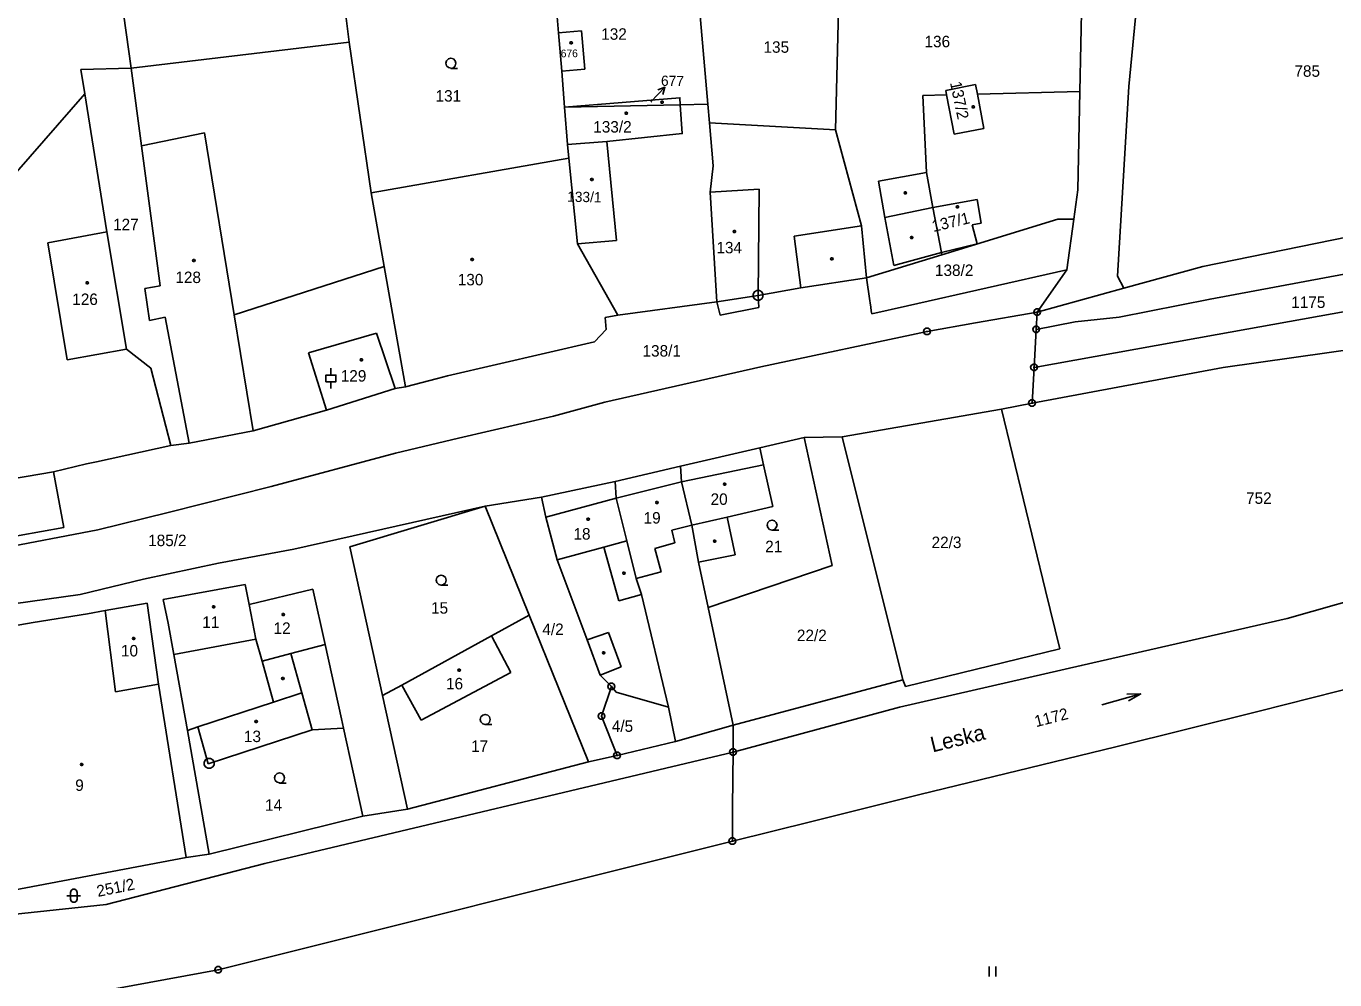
# Model space of a CAD drawing. Extents: x -812394 to -807601, y -1013098 to -1009266.
# Drawn here: x -809612.2 to -809418.3, y -1010813 to -1010671.6 of the extents above; entities that cross this region are included whole.
import ezdxf

# ---------------------------------------------------------------- set-up
doc = ezdxf.new("R2010")
doc.units = 0
for name, color, linetype in [('KN_HRANICE', 7, 'Continuous'), ('KN_KULTURY', 7, 'Continuous'), ('KN_MEZNIKY', 7, 'Continuous'), ('KN_PARCELY', 7, 'Continuous'), ('KN_SLUCKY', 7, 'Continuous')]:
    doc.layers.add(name, color=color, linetype=linetype)

# ---------------------------------------------------------------- blocks, each defined once
blk = doc.blocks.new('101')
blk.add_line((-0.05, 0), (0.05, 0))
blk.add_lwpolyline([(0.19, 0.72), (0.53, 0.53), (0.72, 0.19), (0.72, -0.2), (0.53, -0.54), (0.19, -0.73), (-0.2, -0.73), (-0.54, -0.54), (-0.73, -0.2), (-0.73, 0.19), (-0.54, 0.53), (-0.2, 0.72), (0.19, 0.72)])
blk = doc.blocks.new('304')
blk.add_lwpolyline([(0, 0), (-0.38, 0.1), (-0.65, 0.37), (-0.75, 0.74), (-0.65, 1.11), (-0.38, 1.38), (-0.01, 1.48), (0.36, 1.38), (0.63, 1.11), (0.73, 0.73), (0.63, 0.35), (0.36, 0.08), (-0.02, -0.02), (0.98, -0.02)])
blk = doc.blocks.new('306')
for p, q in [((-0.5, 1.5), (-0.5, 0)), ((0.5, 0), (0.5, 1.5))]:
    blk.add_line(p, q)
blk = doc.blocks.new('316')
for points in [[(-0.5, 1.5), (-0.4, 1.79), (-0.15, 1.97), (0.16, 1.97), (0.41, 1.79), (0.51, 1.5), (0.51, 0.5), (0.41, 0.21), (0.16, 0.03), (-0.15, 0.03), (-0.4, 0.21), (-0.5, 0.5), (-0.5, 1.5)], [(-1, 1), (0.27, 1), (1, 1)]]:
    blk.add_lwpolyline(points)
blk = doc.blocks.new('NAHRADNI_SYMBOL')
blk.add_lwpolyline([(0.09, 0.15), (0.18, 0), (0.09, -0.15), (-0.09, -0.15), (-0.18, 0), (-0.09, 0.15), (0.09, 0.15)])
blk = doc.blocks.new('802')
blk.add_line((-3, 0), (3, 0))
blk.add_lwpolyline([(1, 0.5), (3, 0), (1, -0.5)])
blk = doc.blocks.new('10292')
blk.add_line((0, 3), (0, 0))
blk.add_lwpolyline([(-0.5, 2), (0, 3), (0.5, 2)])
blk = doc.blocks.new('318')
blk.add_line((0, 2), (0, 3))
blk.add_lwpolyline([(0, 0), (0, 1), (-0.75, 1), (-0.75, 2), (0, 2), (0.75, 2), (0.75, 1), (0, 1)])
blk = doc.blocks.new('402')
blk.add_lwpolyline([(0.09, 0.15), (0.18, 0), (0.09, -0.15), (-0.09, -0.15), (-0.18, 0), (-0.09, 0.15), (0.09, 0.15)])
blk = doc.blocks.new('105')
blk.add_line((-0.12, 0), (0.12, 0))
blk.add_lwpolyline([(0.15, 0.48), (0.4, 0.3), (0.5, 0.01), (0.4, -0.28), (0.15, -0.46), (-0.16, -0.46), (-0.41, -0.28), (-0.51, 0.01), (-0.41, 0.3), (-0.16, 0.48), (0.15, 0.48)])

msp = doc.modelspace()

# ---------------------------------------------------------------- linework, layer by layer
at = {"layer": 'KN_HRANICE'}
for p, q in [((-809448.82, -1010680.59), (-809445.9, -1010650.77)), ((-809511.21, -1010683.19), (-809513.45, -1010657.55)), ((-809491.57, -1010658.3), (-809492.27, -1010687)), ((-809534.45, -1010658.78), (-809533.33, -1010672.61)), ((-809564.36, -1010674), (-809565.97, -1010661.03)), ((-809456.08, -1010681.32), (-809455.72, -1010664.14)), ((-809598.46, -1010664.88), (-809596.67, -1010677.83)), ((-809561.08, -1010696.34), (-809564.36, -1010674)), ((-809533.33, -1010672.61), (-809532.87, -1010678.29)), ((-809596.67, -1010677.83), (-809604.12, -1010678.05)), ((-809604.12, -1010678.05), (-809603.55, -1010681.64)), ((-809596.67, -1010677.83), (-809595.14, -1010689.36)), ((-809532.87, -1010678.29), (-809532.44, -1010683.62)), ((-809603.55, -1010681.64), (-809600.29, -1010702.1)), ((-809479.37, -1010681.9), (-809475.82, -1010681.81)), ((-809478.82, -1010693.3), (-809479.37, -1010681.9)), ((-809475.94, -1010681.16), (-809471.53, -1010680.26)), ((-809475.82, -1010681.81), (-809475.94, -1010681.16)), ((-809474.7, -1010687.64), (-809475.82, -1010681.81)), ((-809471.53, -1010680.26), (-809471.26, -1010681.7)), ((-809471.26, -1010681.7), (-809456.08, -1010681.32)), ((-809471.26, -1010681.7), (-809470.29, -1010686.8)), ((-809456.4, -1010695.91), (-809456.08, -1010681.32)), ((-809450.49, -1010708.71), (-809448.82, -1010680.59)), ((-809532.44, -1010683.62), (-809515.29, -1010683.27)), ((-809532.44, -1010683.62), (-809531.99, -1010689.19)), ((-809515.29, -1010683.27), (-809511.21, -1010683.19)), ((-809510.97, -1010685.95), (-809511.21, -1010683.19)), ((-809492.27, -1010687), (-809510.97, -1010685.95)), ((-809510.41, -1010692.32), (-809510.97, -1010685.95)), ((-809492.27, -1010687), (-809488.44, -1010701.23)), ((-809470.29, -1010686.8), (-809474.7, -1010687.64)), ((-809595.14, -1010689.36), (-809592.38, -1010710.12)), ((-809531.99, -1010689.19), (-809526.16, -1010688.74)), ((-809531.79, -1010691.19), (-809531.99, -1010689.19)), ((-809561.08, -1010696.34), (-809531.79, -1010691.19)), ((-809530.54, -1010703.91), (-809531.79, -1010691.19)), ((-809510.85, -1010696.24), (-809510.41, -1010692.32)), ((-809485.94, -1010694.61), (-809478.82, -1010693.3)), ((-809484.96, -1010700.01), (-809485.94, -1010694.61)), ((-809561.08, -1010696.34), (-809559.16, -1010707.24)), ((-809509.86, -1010712.52), (-809510.85, -1010696.24)), ((-809456.4, -1010695.91), (-809456.99, -1010700.24)), ((-809488.44, -1010701.23), (-809487.68, -1010708.94)), ((-809483.66, -1010707.09), (-809484.96, -1010700.01)), ((-809476.51, -1010705.51), (-809459.32, -1010700.23)), ((-809459.32, -1010700.23), (-809456.99, -1010700.24)), ((-809456.99, -1010700.24), (-809458, -1010707.77)), ((-809600.29, -1010702.1), (-809597.34, -1010719.54)), ((-809413.39, -1010702.26), (-809437.86, -1010707.26)), ((-809530.54, -1010703.91), (-809524.53, -1010714.47)), ((-809476.56, -1010705.21), (-809483.66, -1010707.09)), ((-809476.56, -1010705.21), (-809476.51, -1010705.51)), ((-809487.68, -1010708.94), (-809476.51, -1010705.51)), ((-809581.39, -1010714.41), (-809559.16, -1010707.24)), ((-809559.16, -1010707.24), (-809556, -1010725.11)), ((-809497.45, -1010710.44), (-809487.68, -1010708.94)), ((-809487.2, -1010712.35), (-809487.68, -1010708.94)), ((-809481.63, -1010713.11), (-809458, -1010707.77)), ((-809462.39, -1010714.03), (-809458, -1010707.77)), ((-809449.57, -1010710.49), (-809450.49, -1010708.71)), ((-809437.86, -1010707.26), (-809449.57, -1010710.49)), ((-809592.38, -1010710.12), (-809594.66, -1010710.54)), ((-809594.66, -1010710.54), (-809593.93, -1010715.27)), ((-809503.76, -1010711.54), (-809497.45, -1010710.44)), ((-809449.57, -1010710.49), (-809462.39, -1010714.03)), ((-809524.53, -1010714.47), (-809509.86, -1010712.52)), ((-809509.86, -1010712.52), (-809509.39, -1010714.47)), ((-809503.65, -1010713.32), (-809503.76, -1010711.54)), ((-809487.15, -1010712.67), (-809487.2, -1010712.35)), ((-809487.06, -1010713.28), (-809487.15, -1010712.67)), ((-809593.93, -1010715.27), (-809591.65, -1010714.79)), ((-809591.65, -1010714.79), (-809588.06, -1010733.47)), ((-809578.59, -1010731.65), (-809581.39, -1010714.41)), ((-809526.41, -1010714.85), (-809524.53, -1010714.47)), ((-809526.26, -1010716.6), (-809526.41, -1010714.85)), ((-809509.39, -1010714.47), (-809503.65, -1010713.32)), ((-809486.99, -1010713.83), (-809487.06, -1010713.28)), ((-809486.92, -1010714.3), (-809486.99, -1010713.83)), ((-809486.92, -1010714.3), (-809481.63, -1010713.11)), ((-809462.39, -1010714.03), (-809471.53, -1010715.63)), ((-809462.54, -1010716.59), (-809462.39, -1010714.03)), ((-809528.01, -1010718.45), (-809526.26, -1010716.6)), ((-809503.35, -1010722.13), (-809478.73, -1010716.9)), ((-809471.53, -1010715.63), (-809478.73, -1010716.9)), ((-809462.86, -1010722.22), (-809462.54, -1010716.59)), ((-809434.83, -1010722.26), (-809386.46, -1010715.35)), ((-809549.8, -1010723.5), (-809528.01, -1010718.45)), ((-809597.34, -1010719.54), (-809593.76, -1010722.34)), ((-809593.76, -1010722.34), (-809590.8, -1010733.81)), ((-809526.46, -1010727.38), (-809503.35, -1010722.13)), ((-809463.16, -1010727.52), (-809462.86, -1010722.22)), ((-809463.16, -1010727.52), (-809434.83, -1010722.26)), ((-809556, -1010725.11), (-809551.26, -1010723.86)), ((-809551.26, -1010723.86), (-809549.8, -1010723.5)), ((-809567.73, -1010728.55), (-809557.57, -1010725.36)), ((-809557.57, -1010725.36), (-809556, -1010725.11)), ((-809567.73, -1010728.55), (-809578.59, -1010731.65)), ((-809534.09, -1010729.46), (-809526.46, -1010727.38)), ((-809491.31, -1010732.5), (-809467.68, -1010728.42)), ((-809467.68, -1010728.42), (-809463.16, -1010727.52)), ((-809548.16, -1010732.72), (-809534.09, -1010729.46)), ((-809578.59, -1010731.65), (-809588.06, -1010733.47)), ((-809590.8, -1010733.81), (-809601.82, -1010736.22)), ((-809588.06, -1010733.47), (-809590.8, -1010733.81)), ((-809557.49, -1010734.93), (-809548.16, -1010732.72)), ((-809515.24, -1010736.89), (-809503.51, -1010734.14)), ((-809503.51, -1010734.14), (-809496.94, -1010732.6)), ((-809502.98, -1010736.65), (-809503.51, -1010734.14)), ((-809496.94, -1010732.6), (-809491.31, -1010732.5)), ((-809496.94, -1010732.6), (-809492.77, -1010751.6)), ((-809491.31, -1010732.5), (-809482.31, -1010768.54)), ((-809601.82, -1010736.22), (-809603.28, -1010736.54)), ((-809575.93, -1010739.9), (-809557.49, -1010734.93)), ((-809618.66, -1010739.51), (-809608.17, -1010737.7)), ((-809608.17, -1010737.7), (-809603.28, -1010736.54)), ((-809608.17, -1010737.7), (-809606.66, -1010745.99)), ((-809524.96, -1010739.16), (-809515.24, -1010736.89)), ((-809515.12, -1010739.21), (-809515.24, -1010736.89)), ((-809502.98, -1010736.65), (-809501.59, -1010742.84)), ((-809591.21, -1010743.76), (-809575.93, -1010739.9)), ((-809535.88, -1010741.49), (-809524.96, -1010739.16)), ((-809524.82, -1010741.63), (-809524.96, -1010739.16)), ((-809513.6, -1010745.64), (-809515.12, -1010739.21)), ((-809544.23, -1010742.79), (-809535.88, -1010741.49)), ((-809535.88, -1010741.49), (-809535.22, -1010744.44)), ((-809524.82, -1010741.63), (-809523.2, -1010747.95)), ((-809601.6, -1010746.29), (-809591.21, -1010743.76)), ((-809544.23, -1010742.79), (-809572.56, -1010749.19)), ((-809564.25, -1010748.81), (-809544.23, -1010742.79)), ((-809544.23, -1010742.79), (-809537.7, -1010758.97)), ((-809501.59, -1010742.84), (-809508.37, -1010744.41)), ((-809606.66, -1010745.99), (-809626.64, -1010749.55)), ((-809535.22, -1010744.44), (-809533.52, -1010750.77)), ((-809512.59, -1010751.13), (-809513.6, -1010745.64)), ((-809508.37, -1010744.41), (-809507.14, -1010750.01)), ((-809621.25, -1010750.05), (-809601.6, -1010746.29)), ((-809572.56, -1010749.19), (-809583.73, -1010751.27)), ((-809559.42, -1010770.87), (-809564.25, -1010748.81)), ((-809523.2, -1010747.95), (-809521.85, -1010753.55)), ((-809583.73, -1010751.27), (-809594.82, -1010753.62)), ((-809533.52, -1010750.77), (-809529.09, -1010762.64)), ((-809512.59, -1010751.13), (-809507.14, -1010750.01)), ((-809512.59, -1010751.13), (-809511.16, -1010757.85)), ((-809492.77, -1010751.6), (-809511.16, -1010757.85)), ((-809594.82, -1010753.62), (-809604.22, -1010755.92)), ((-809521.85, -1010753.55), (-809521.03, -1010755.88)), ((-809591.91, -1010756.66), (-809579.76, -1010754.43)), ((-809579.76, -1010754.43), (-809579.19, -1010757.38)), ((-809579.19, -1010757.38), (-809569.76, -1010755.12)), ((-809569.76, -1010755.12), (-809567.94, -1010763.34)), ((-809619.48, -1010758), (-809604.22, -1010755.92)), ((-809594.29, -1010757.19), (-809600.5, -1010758.29)), ((-809592.64, -1010769.19), (-809594.29, -1010757.19)), ((-809591.2, -1010760.14), (-809591.91, -1010756.66)), ((-809579.19, -1010757.38), (-809578.18, -1010762.54)), ((-809521.03, -1010755.88), (-809517.06, -1010772.62)), ((-809611.19, -1010760.06), (-809603.15, -1010758.78)), ((-809603.15, -1010758.78), (-809600.5, -1010758.29)), ((-809600.5, -1010758.29), (-809598.99, -1010770.33)), ((-809543.29, -1010762.05), (-809537.7, -1010758.97)), ((-809537.7, -1010758.97), (-809528.91, -1010780.74)), ((-809511.16, -1010757.85), (-809507.45, -1010775.29)), ((-809619.76, -1010761.5), (-809611.19, -1010760.06)), ((-809590.34, -1010764.82), (-809591.2, -1010760.14)), ((-809577.28, -1010765.78), (-809578.18, -1010762.54)), ((-809572.99, -1010764.66), (-809567.94, -1010763.34)), ((-809567.94, -1010763.34), (-809565.5, -1010774.33)), ((-809556.56, -1010769.35), (-809543.29, -1010762.05)), ((-809543.29, -1010762.05), (-809540.4, -1010767.48)), ((-809529.09, -1010762.64), (-809527.15, -1010767.85)), ((-809590.34, -1010764.82), (-809588.33, -1010776.05)), ((-809577.28, -1010765.78), (-809572.99, -1010764.66)), ((-809481.91, -1010769.54), (-809459.07, -1010763.94)), ((-809575.59, -1010771.87), (-809577.28, -1010765.78)), ((-809598.99, -1010770.33), (-809592.64, -1010769.19)), ((-809588.54, -1010794.9), (-809592.64, -1010769.19)), ((-809540.4, -1010767.48), (-809553.7, -1010774.56)), ((-809527.15, -1010767.85), (-809525.51, -1010769.54)), ((-809507.45, -1010775.29), (-809482.31, -1010768.54)), ((-809482.31, -1010768.54), (-809481.91, -1010769.54)), ((-809556.56, -1010769.35), (-809559.42, -1010770.87)), ((-809555.73, -1010787.74), (-809559.42, -1010770.87)), ((-809556.56, -1010769.35), (-809553.7, -1010774.56)), ((-809526.96, -1010773.94), (-809525.51, -1010769.54)), ((-809525.51, -1010769.54), (-809524.78, -1010770.4)), ((-809524.78, -1010770.4), (-809517.06, -1010772.62)), ((-809586.77, -1010775.53), (-809575.59, -1010771.87)), ((-809517.06, -1010772.62), (-809516.02, -1010777.68)), ((-809565.5, -1010774.33), (-809565.19, -1010775.74)), ((-809524.66, -1010779.77), (-809526.96, -1010773.94)), ((-809586.77, -1010775.53), (-809588.33, -1010776.05)), ((-809588.33, -1010776.05), (-809585.11, -1010794.39)), ((-809586.77, -1010775.53), (-809585.25, -1010781)), ((-809585.25, -1010781), (-809569.85, -1010775.96)), ((-809569.85, -1010775.96), (-809565.19, -1010775.74)), ((-809565.19, -1010775.74), (-809562.33, -1010788.78)), ((-809516.02, -1010777.68), (-809507.45, -1010775.29)), ((-809507.48, -1010779.27), (-809507.45, -1010775.29)), ((-809524.66, -1010779.77), (-809516.02, -1010777.68)), ((-809576.87, -1010795.8), (-809507.48, -1010779.27)), ((-809555.73, -1010787.74), (-809528.91, -1010780.74)), ((-809528.91, -1010780.74), (-809524.66, -1010779.77)), ((-809507.51, -1010783.2), (-809507.48, -1010779.27)), ((-809507.54, -1010787.61), (-809507.51, -1010783.2)), ((-809562.33, -1010788.78), (-809555.73, -1010787.74)), ((-809507.57, -1010792.49), (-809507.54, -1010787.61)), ((-809585.11, -1010794.39), (-809562.33, -1010788.78)), ((-809507.57, -1010792.49), (-809495.79, -1010789.54)), ((-809583.77, -1010811.56), (-809507.57, -1010792.49)), ((-809588.54, -1010794.9), (-809585.11, -1010794.39)), ((-809615.96, -1010800.09), (-809588.54, -1010794.9)), ((-809600.38, -1010801.89), (-809576.87, -1010795.8)), ((-809600.38, -1010801.89), (-809643.49, -1010806.47)), ((-809609.07, -1010816.23), (-809583.77, -1010811.56))]:
    msp.add_line(p, q, dxfattribs=at)
for points in [[(-809533.33, -1010672.61), (-809529.94, -1010672.33), (-809529.46, -1010677.99), (-809532.87, -1010678.29)], [(-809623.13, -1010728.35), (-809625.78, -1010708.61), (-809623.83, -1010704.87), (-809603.55, -1010681.64)], [(-809532.44, -1010683.62), (-809515.36, -1010682.23), (-809515.29, -1010683.27)], [(-809526.16, -1010688.74), (-809514.99, -1010687.55), (-809515.29, -1010683.27)], [(-809386.86, -1010717.18), (-809390.64, -1010734.74), (-809392.82, -1010743.13), (-809395.75, -1010747.43), (-809400.98, -1010751.89), (-809410.38, -1010755.21), (-809425.36, -1010759.45), (-809455.87, -1010766.45), (-809482.83, -1010772.6), (-809507.48, -1010779.27)], [(-809459.07, -1010763.94), (-809461.16, -1010755.31), (-809467.68, -1010728.42)], [(-809429.53, -1010773.18), (-809413.92, -1010769.26), (-809389.38, -1010761.78)], [(-809495.79, -1010789.54), (-809479.79, -1010785.54), (-809450.75, -1010778.5), (-809429.53, -1010773.18)]]:
    msp.add_lwpolyline(points, dxfattribs=at)
at = {"layer": 'KN_SLUCKY'}
for p, q in [((-809596.67, -1010677.83), (-809564.36, -1010674)), ((-809585.78, -1010687.46), (-809595.14, -1010689.36)), ((-809581.39, -1010714.41), (-809585.78, -1010687.46)), ((-809526.16, -1010688.74), (-809524.76, -1010703.42)), ((-809478.82, -1010693.3), (-809477.86, -1010698.52)), ((-809503.61, -1010695.79), (-809510.85, -1010696.24)), ((-809503.76, -1010711.54), (-809503.61, -1010695.79)), ((-809477.86, -1010698.52), (-809471.32, -1010697.32)), ((-809471.32, -1010697.32), (-809470.68, -1010700.85)), ((-809484.96, -1010700.01), (-809477.86, -1010698.52)), ((-809477.86, -1010698.52), (-809476.56, -1010705.21)), ((-809498.4, -1010702.75), (-809488.44, -1010701.23)), ((-809470.68, -1010700.85), (-809472.02, -1010701.1)), ((-809472.02, -1010701.1), (-809471.31, -1010703.88)), ((-809600.29, -1010702.1), (-809609, -1010703.76)), ((-809497.45, -1010710.44), (-809498.4, -1010702.75)), ((-809609, -1010703.76), (-809606.14, -1010721.1)), ((-809524.76, -1010703.42), (-809530.54, -1010703.91)), ((-809471.31, -1010703.88), (-809476.56, -1010705.21)), ((-809509.86, -1010712.52), (-809503.76, -1010711.54)), ((-809560.3, -1010717.14), (-809570.39, -1010720.06)), ((-809557.57, -1010725.36), (-809560.3, -1010717.14)), ((-809606.14, -1010721.1), (-809597.34, -1010719.54)), ((-809570.39, -1010720.06), (-809567.73, -1010728.55)), ((-809515.12, -1010739.21), (-809502.98, -1010736.65)), ((-809524.82, -1010741.63), (-809515.12, -1010739.21)), ((-809535.22, -1010744.44), (-809524.82, -1010741.63)), ((-809513.6, -1010745.64), (-809516.56, -1010746.35)), ((-809513.6, -1010745.64), (-809508.37, -1010744.41)), ((-809516.09, -1010748.24), (-809516.56, -1010746.35)), ((-809533.52, -1010750.77), (-809526.63, -1010748.89)), ((-809526.63, -1010748.89), (-809523.2, -1010747.95)), ((-809524.42, -1010756.83), (-809526.63, -1010748.89)), ((-809519.06, -1010749.09), (-809516.09, -1010748.24)), ((-809518.14, -1010752.55), (-809519.06, -1010749.09)), ((-809521.85, -1010753.55), (-809518.14, -1010752.55)), ((-809521.03, -1010755.88), (-809524.42, -1010756.83)), ((-809525.94, -1010761.52), (-809529.09, -1010762.64)), ((-809524.07, -1010766.63), (-809525.94, -1010761.52)), ((-809578.18, -1010762.54), (-809590.34, -1010764.82)), ((-809571.37, -1010770.49), (-809572.99, -1010764.66)), ((-809527.15, -1010767.85), (-809524.07, -1010766.63)), ((-809575.59, -1010771.87), (-809571.37, -1010770.49)), ((-809571.37, -1010770.49), (-809569.85, -1010775.96))]:
    msp.add_line(p, q, dxfattribs=at)
for points in [[(-809462.54, -1010716.59), (-809456.78, -1010715.47), (-809450.24, -1010714.77), (-809436.78, -1010712.1), (-809413.21, -1010707.7), (-809386.06, -1010702.58)], [(-809385.19, -1010708.29), (-809412.36, -1010713.13), (-809435.74, -1010717.37), (-809462.86, -1010722.22)]]:
    msp.add_lwpolyline(points, dxfattribs=at)

# ---------------------------------------------------------------- block references
at = {"layer": 'KN_KULTURY'}
for name, p in [('402', (-809531.46, -1010674.08)), ('304', (-809549.27, -1010677.86)), ('402', (-809517.99, -1010682.9)), ('402', (-809471.88, -1010683.59)), ('402', (-809523.3, -1010684.54)), ('402', (-809528.4, -1010694.35)), ('402', (-809481.95, -1010696.36)), ('402', (-809474.22, -1010698.43)), ('402', (-809507.27, -1010702.09)), ('402', (-809481.01, -1010702.97)), ('402', (-809587.39, -1010706.38)), ('NAHRADNI_SYMBOL', (-809546.13, -1010706.21)), ('402', (-809492.83, -1010706.14)), ('402', (-809603.18, -1010709.67)), ('318', (-809567.07, -1010725.36)), ('402', (-809562.55, -1010721.09)), ('402', (-809508.71, -1010739.53)), ('402', (-809518.76, -1010742.26)), ('402', (-809528.95, -1010744.75)), ('304', (-809501.69, -1010746.34)), ('402', (-809510.19, -1010747.99)), ('304', (-809550.72, -1010754.51)), ('402', (-809523.65, -1010752.72)), ('402', (-809584.45, -1010757.72)), ('NAHRADNI_SYMBOL', (-809574.13, -1010758.87)), ('402', (-809596.3, -1010762.41)), ('402', (-809526.65, -1010764.55)), ('402', (-809548.06, -1010767.1)), ('402', (-809574.2, -1010768.35)), ('402', (-809578.14, -1010774.75)), ('304', (-809544.19, -1010775.16)), ('NAHRADNI_SYMBOL', (-809604.01, -1010781.1)), ('304', (-809574.67, -1010783.84)), ('316', (-809605.18, -1010801.57)), ('306', (-809469.01, -1010812.57))]:
    msp.add_blockref(name, p, dxfattribs=at)
at = {"layer": 'KN_KULTURY', "rotation": 15.527156}
msp.add_blockref('802', (-809449.95, -1010771.45), dxfattribs=at)
at = {"layer": 'KN_MEZNIKY'}
for name, p in [('101', (-809503.76, -1010711.54)), ('105', (-809462.39, -1010714.03)), ('105', (-809478.73, -1010716.9)), ('105', (-809462.54, -1010716.59)), ('105', (-809462.86, -1010722.22)), ('105', (-809463.16, -1010727.52)), ('105', (-809525.51, -1010769.54)), ('105', (-809526.96, -1010773.94)), ('105', (-809507.48, -1010779.27)), ('101', (-809585.1, -1010780.94)), ('105', (-809524.66, -1010779.77)), ('105', (-809507.57, -1010792.49)), ('105', (-809583.77, -1010811.56))]:
    msp.add_blockref(name, p, dxfattribs=at)
at = {"layer": 'KN_PARCELY', "rotation": -43.72729700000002}
msp.add_blockref('10292', (-809519.64, -1010682.85), dxfattribs=at)

# ---------------------------------------------------------------- texts
at = {"layer": 'KN_PARCELY'}
for s, height, p in [('132', 1.7, (-809527.01, -1010673.64)), ('135', 1.7, (-809502.96, -1010675.57)), ('136', 1.7, (-809479.1, -1010674.75)), ('785', 1.7, (-809424.28, -1010679.13)), ('131', 1.7, (-809551.56, -1010682.81)), ('677', 0.1, (-809519.62, -1010682.95)), ('133/2', 1.7, (-809528.19, -1010687.4)), ('127', 1.7, (-809599.35, -1010701.88)), ('134', 1.7, (-809509.94, -1010705.31)), ('138/2', 1.7, (-809477.55, -1010708.67)), ('128', 1.7, (-809590.12, -1010709.72)), ('130', 1.7, (-809548.27, -1010710.06)), ('126', 1.7, (-809605.4, -1010712.97)), ('1175', 1.7, (-809424.75, -1010713.41)), ('138/1', 1.7, (-809520.89, -1010720.62)), ('129', 1.7, (-809565.61, -1010724.33)), ('20', 1.7, (-809510.8, -1010742.61)), ('752', 1.7, (-809431.45, -1010742.46)), ('19', 1.7, (-809520.73, -1010745.38)), ('185/2', 1.7, (-809594.15, -1010748.73)), ('18', 1.7, (-809531.12, -1010747.76)), ('21', 1.7, (-809502.71, -1010749.63)), ('22/3', 1.7, (-809478.05, -1010749.02)), ('15', 1.7, (-809552.23, -1010758.74)), ('11', 1.7, (-809586.13, -1010760.85)), ('12', 1.7, (-809575.57, -1010761.74)), ('4/2', 1.7, (-809535.74, -1010761.91)), ('22/2', 1.7, (-809498.01, -1010762.81)), ('10', 1.7, (-809598.18, -1010765.09)), ('16', 1.7, (-809550.01, -1010769.97)), ('4/5', 1.7, (-809525.44, -1010776.27)), ('13', 1.7, (-809579.96, -1010777.79)), ('17', 1.7, (-809546.3, -1010779.25)), ('9', 1.7, (-809604.96, -1010785.03)), ('14', 1.7, (-809576.84, -1010787.98))]:
    msp.add_text(s, height=height, dxfattribs=at).set_placement(p)
for s, height, rotation, p in [('676', 1.14, 0.401, (-809533.01, -1010676.24)), ('677', 1.52, 359.015, (-809518.16, -1010680.47)), ('137/2', 1.7, 281.838, (-809475.33, -1010680)), ('133/1', 1.52, 358.672, (-809532.07, -1010697.65)), ('137/1', 1.7, 13.407, (-809477.79, -1010702.15)), ('1172', 1.7, 14.324, (-809462.56, -1010775.58)), ('Leska', 2.3, 13.808, (-809477.9, -1010779.33)), ('251/2', 1.7, 11.574, (-809601.6, -1010800.76))]:
    msp.add_text(s, height=height, rotation=rotation, dxfattribs=at).set_placement(p)

doc.saveas('drawing.dxf')
